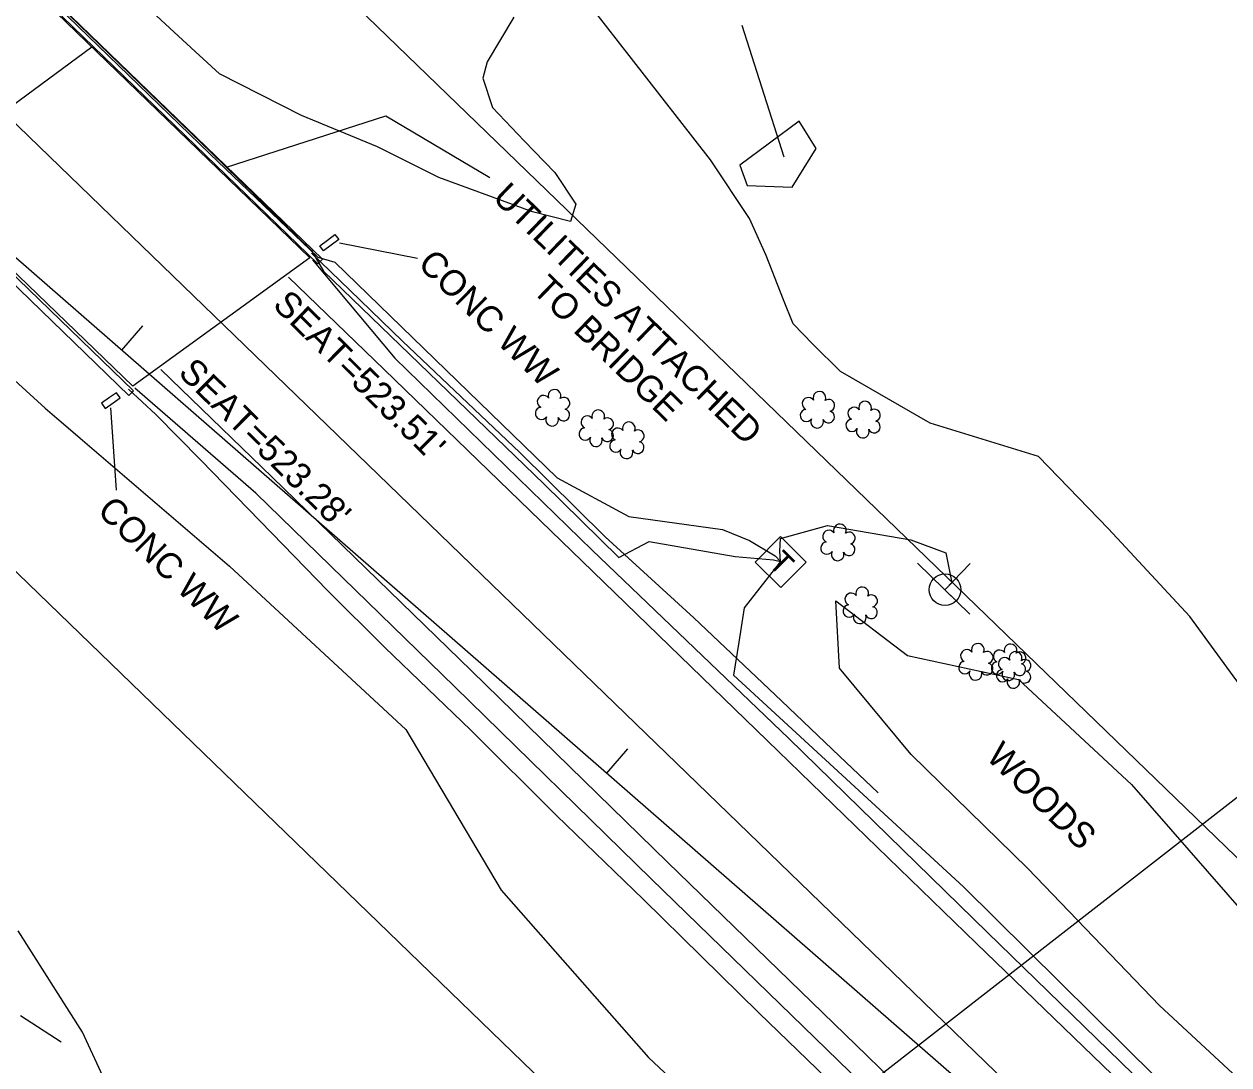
# Model space of a CAD drawing. Extents: x 1977096 to 1980486, y 845025 to 848427.
# Drawn here: x 1979075.8 to 1979263.1, y 846243.1 to 846404.9 of the extents above; entities that cross this region are included whole.
import ezdxf

# ---------------------------------------------------------------- set-up
doc = ezdxf.new("R2010")
doc.units = 0
for name, color, linetype in [('Exist Guardrail', 7, 'Continuous'), ('Exist Horizontal Alignment', 7, 'Continuous'), ('Exist Horizontal Baseline Alignment', 7, 'Continuous'), ('Exist Horizontal Baseline Alignment Tick small', 7, 'Continuous'), ('Exist Hydro Disappearing Stream CELL', 7, 'Continuous'), ('Exist Other Culture Area Outline', 7, 'Continuous'), ('Exist Other Culture Area Outline Text', 7, 'Continuous'), ('Exist Property Same Owner Line CELL', 7, 'Continuous'), ('Exist Right of Way Line', 7, 'Continuous'), ('Exist Roads Curbs', 7, 'Continuous'), ('Exist Roads EOP', 7, 'Continuous'), ('Exist Roads EOT', 7, 'Continuous'), ('Exist Structure Major Bridge Seam', 7, 'Continuous'), ('Exist Structure Major Bridge Seat Top Elevation', 7, 'Continuous'), ('Exist Structure Major Bridge WW', 7, 'Continuous'), ('Exist Structure Major Bridge WW Text', 7, 'Continuous'), ('Exist Structure Major Deck Tunnel Box Culvert', 7, 'Continuous'), ('Exist Utilities Power Joint Use Telephone CELL', 7, 'Continuous'), ('Exist Utilities Telephone Pedestal CELL', 7, 'Continuous'), ('Exist Utilities Telephone UG Cable SUE LOS B', 7, 'Continuous'), ('Exist Utilities Telephone UG Cable SUE LOS C', 7, 'Continuous'), ('Exist Vegetation Shrub CELL', 7, 'Continuous'), ('Exist Vegetation Woods Line', 7, 'Continuous'), ('Exist Vegetation Woods Line Text', 7, 'Continuous')]:
    doc.layers.add(name, color=color, linetype=linetype)

msp = doc.modelspace()

# ---------------------------------------------------------------- linework, layer by layer
at = {"layer": 'Exist Guardrail'}
for points in [[(1979120.53, 846369.31), (1979126.46, 846363.56), (1979134.68, 846355.61), (1979152.9, 846338.29), (1979166.16, 846325.21), (1979179.93, 846312.61), (1979193.55, 846299.73), (1979202.61, 846291.11), (1979208.59, 846285.42)], [(1979259.69, 846182.69), (1979249.62, 846192.61), (1979236.12, 846206.04), (1979223.28, 846219.01), (1979208.19, 846233.69), (1979190.05, 846251.2), (1979172.15, 846268.81), (1979158.61, 846281.9), (1979145.28, 846295.15), (1979131.93, 846308.01), (1979123.06, 846316.81), (1979114.36, 846325.76), (1979103.32, 846337.1), (1979096.34, 846344.2), (1979092.05, 846348.15)]]:
    msp.add_lwpolyline(points, dxfattribs=at)
at = {"layer": 'Exist Horizontal Alignment'}
msp.add_line((1978489.47, 846954.95), (1979491.73, 845985.98), dxfattribs=at)
at = {"layer": 'Exist Horizontal Baseline Alignment'}
msp.add_line((1978896.27, 846524.09), (1979767.77, 845764.02), dxfattribs=at)
at = {"layer": 'Exist Horizontal Baseline Alignment Tick small'}
for p, q in [((1979091.04, 846354.22), (1979094.32, 846357.99)), ((1979166.4, 846288.49), (1979169.69, 846292.26))]:
    msp.add_line(p, q, dxfattribs=at)
at = {"layer": 'Exist Hydro Disappearing Stream CELL'}
msp.add_line((1979075.29, 846250.81), (1979081.63, 846246.73), dxfattribs=at)
at = {"layer": 'Exist Other Culture Area Outline'}
msp.add_lwpolyline([(1979196.3, 846389.82), (1979187.11, 846382.94), (1979188.24, 846379.79), (1979195.25, 846379.53), (1979198.97, 846385.57), (1979196.3, 846389.82)], dxfattribs=at)
at = {"layer": 'Exist Other Culture Area Outline Text'}
msp.add_line((1979194, 846384.23), (1979187.46, 846404.69), dxfattribs=at)
msp.add_lwpolyline([(1979107.32, 846382.64), (1979132.06, 846390.64), (1979148.22, 846381.07)], dxfattribs=at)
at = {"layer": 'Exist Property Same Owner Line CELL'}
msp.add_lwpolyline([(1979292.37, 846303.36), (1979303.7, 846315.26), (1979077.67, 846139.38), (1979089, 846151.29)], dxfattribs=at)
at = {"layer": 'Exist Right of Way Line'}
for p, q in [((1978524.22, 846990.9), (1979641.56, 845910.68)), ((1978965.22, 846425.46), (1979456.98, 845950.04))]:
    msp.add_line(p, q, dxfattribs=at)
at = {"layer": 'Exist Roads Curbs'}
for p, q in [((1978950.41, 846534.47), (1979122.22, 846368.35)), ((1978949.71, 846533.75), (1979121.53, 846367.63)), ((1978921, 846514.01), (1979092.85, 846347.88)), ((1978920.3, 846513.29), (1979092.15, 846347.16)), ((1979121.53, 846367.63), (1979122.22, 846368.35)), ((1979092.15, 846347.16), (1979092.85, 846347.88))]:
    msp.add_line(p, q, dxfattribs=at)
at = {"layer": 'Exist Roads EOP'}
for points in [[(1979120.65, 846368.26), (1979133.49, 846352.99), (1979164.17, 846323.1), (1979194.73, 846293.87), (1979225.61, 846263.72), (1979255.68, 846234.45), (1979285.73, 846205.36), (1979315.37, 846176.53), (1979345.8, 846147.12), (1979377.72, 846116.63), (1979407.25, 846087.83), (1979438.13, 846057.9), (1979467.93, 846029.23), (1979498.8, 845999.18)], [(1979477.6, 845978.01), (1979446.84, 846007.88), (1979416.62, 846037.35), (1979386.7, 846066.33), (1979356.86, 846095.38), (1979326.24, 846125.39), (1979294.45, 846155.84), (1979265.05, 846184.42), (1979235.05, 846212.58), (1979204.24, 846241.97), (1979173.33, 846272.04), (1979142.8, 846301.86), (1979111.85, 846332.01), (1979093.06, 846348.31)]]:
    msp.add_lwpolyline(points, dxfattribs=at)
at = {"layer": 'Exist Roads EOT'}
for p, q in [((1979116.93, 846365.56), (1979131.83, 846351.23)), ((1979097.1, 846351.23), (1979114.39, 846334.48))]:
    msp.add_line(p, q, dxfattribs=at)
for points in [[(1979131.83, 846351.23), (1979162.6, 846321.41), (1979193.04, 846291.89), (1979223.84, 846262.02), (1979254.08, 846232.84), (1979284.13, 846203.74), (1979313.6, 846175.13), (1979344.26, 846145.52), (1979376, 846114.94), (1979405.65, 846086.18), (1979436.21, 846056.39), (1979465.96, 846027.1), (1979496.86, 845997.11)], [(1979114.39, 846334.48), (1979145.37, 846304.35), (1979175.87, 846274.62), (1979206.9, 846244.54), (1979237.19, 846215.01), (1979267.05, 846186.27), (1979296.58, 846157.89), (1979328.22, 846127.36), (1979359.02, 846097.46), (1979388.76, 846068.61), (1979418.86, 846039.37), (1979449, 846010.07), (1979479.81, 845980.17)]]:
    msp.add_lwpolyline(points, dxfattribs=at)
at = {"layer": 'Exist Structure Major Bridge Seam'}
msp.add_line((1979086.38, 846401.33), (1979058.73, 846380.94), dxfattribs=at)
at = {"layer": 'Exist Structure Major Bridge WW'}
for points in [[(1979121.81, 846370.45), (1979122.99, 846371.33), (1979124.17, 846372.21), (1979124.77, 846371.41), (1979123.59, 846370.53), (1979122.41, 846369.65), (1979121.81, 846370.45)], [(1979090.21, 846347.6), (1979089.14, 846346.86), (1979087.87, 846345.98), (1979088.44, 846345.16), (1979089.71, 846346.04), (1979090.78, 846346.78), (1979090.21, 846347.6)]]:
    msp.add_lwpolyline(points, dxfattribs=at)
at = {"layer": 'Exist Structure Major Bridge WW Text'}
for p, q in [((1979124.89, 846370.88), (1979137, 846368.51)), ((1979089.28, 846345.23), (1979090.17, 846332.47))]:
    msp.add_line(p, q, dxfattribs=at)
at = {"layer": 'Exist Structure Major Deck Tunnel Box Culvert'}
msp.add_lwpolyline([(1978949.98, 846533.2), (1979120.24, 846368.57), (1979092.73, 846348.59), (1978922.38, 846513.01), (1978949.98, 846533.2)], dxfattribs=at)
at = {"layer": 'Exist Utilities Power Joint Use Telephone CELL'}
msp.add_line((1979218.98, 846316.97), (1979218.98, 846316.97), dxfattribs=at)
msp.add_lwpolyline([(1979214.7, 846321.09), (1979222.85, 846313.2), (1979218.97, 846316.96), (1979222.88, 846321.03)], dxfattribs=at)
msp.add_circle((1979218.99, 846316.98), 2.45, dxfattribs=at)
at = {"layer": 'Exist Utilities Telephone Pedestal CELL'}
msp.add_line((1979193.41, 846321.34), (1979193.41, 846321.34), dxfattribs=at)
msp.add_lwpolyline([(1979189.49, 846321.27), (1979193.45, 846317.31), (1979197.4, 846321.27), (1979193.44, 846325.23), (1979189.49, 846321.27)], dxfattribs=at)
at = {"layer": 'Exist Utilities Telephone UG Cable SUE LOS B'}
for points in [[(1978827.65, 846546.54), (1978851.92, 846542.32), (1978879.52, 846535.99), (1978884.35, 846535.6), (1978891.83, 846534.67), (1978899.37, 846538.39), (1978920.22, 846556.85), (1978924.91, 846559.45), (1978950.09, 846536.12), (1978950.33, 846534.15), (1978987.97, 846497.66), (1979030.84, 846456.21), (1979068.41, 846419.87), (1979104.74, 846384.73), (1979121.49, 846368.64), (1979124.13, 846367.89), (1979158.73, 846334.37), (1979169.87, 846328.36), (1979184.39, 846326.33), (1979188.6, 846324.61), (1979192.59, 846322.26), (1979193.41, 846321.34)], [(1979193.41, 846321.34), (1979193.32, 846322.96), (1979193.4, 846324.92), (1979200.74, 846326.97), (1979213.68, 846324.75), (1979219.13, 846322.69), (1979220.06, 846318.06), (1979218.98, 846316.97)]]:
    msp.add_lwpolyline(points, dxfattribs=at)
at = {"layer": 'Exist Utilities Telephone UG Cable SUE LOS C'}
for points in [[(1978816.58, 846668.11), (1978851.59, 846633.51), (1978891.39, 846594.5), (1978926.18, 846560.72), (1978950.49, 846536.73), (1978950.45, 846534.27), (1978988.14, 846497.85), (1979031.03, 846456.38), (1979068.6, 846420.04), (1979104.92, 846384.91), (1979120.52, 846369.7), (1979122.4, 846366.47), (1979156.61, 846333.43), (1979168.3, 846321.97), (1979173, 846324.46), (1979186.35, 846322.12), (1979192.31, 846321.61), (1979193.41, 846321.34)], [(1979193.41, 846321.34), (1979192.65, 846320.39), (1979187.79, 846314.17), (1979186.96, 846308.83), (1979186.13, 846303.7), (1979221.88, 846270.8), (1979256.83, 846236.2), (1979291.06, 846202.44), (1979328.81, 846166.03), (1979367.53, 846128.09), (1979406.07, 846091.3), (1979445.38, 846052.99), (1979477.33, 846021.94)]]:
    msp.add_lwpolyline(points, dxfattribs=at)
at = {"layer": 'Exist Vegetation Shrub CELL'}
for p, q in [((1979158.06, 846345.08), (1979158.06, 846345.08)), ((1979199.24, 846344.76), (1979199.24, 846344.76)), ((1979164.86, 846341.89), (1979164.86, 846341.89)), ((1979206.34, 846343.23), (1979206.34, 846343.23)), ((1979169.62, 846340.02), (1979169.62, 846340.02)), ((1979202.43, 846324.15), (1979202.43, 846324.15)), ((1979205.89, 846314.37), (1979205.89, 846314.37)), ((1979223.87, 846305.59), (1979223.87, 846305.59)), ((1979228.95, 846305.51), (1979228.95, 846305.51)), ((1979229.74, 846304.33), (1979229.74, 846304.33))]:
    msp.add_line(p, q, dxfattribs=at)
for centre, radius, start, end in [((1979156.58, 846346.21), 0.968, 35.8908, 245.4216), ((1979158.29, 846347.12), 0.99, 334.8391, 200.4717), ((1979199.47, 846346.8), 0.99, 334.8391, 200.4717), ((1979156.26, 846344.38), 0.955, 95.1099, 327.9534), ((1979159.73, 846345.95), 0.929, 284.4567, 126.0861), ((1979197.76, 846345.89), 0.968, 35.8908, 245.4216), ((1979200.91, 846345.63), 0.929, 284.4567, 126.0861), ((1979204.86, 846344.36), 0.968, 35.8908, 245.4216), ((1979206.57, 846345.27), 0.99, 334.8391, 200.4717), ((1979157.93, 846343.4), 0.984, 151.2797, 21.387), ((1979159.7, 846344.15), 0.937, 204.9913, 73.4601), ((1979163.38, 846343.02), 0.968, 35.8908, 245.4216), ((1979165.09, 846343.93), 0.99, 334.8391, 200.4717), ((1979166.53, 846342.76), 0.929, 284.4567, 126.0861), ((1979197.44, 846344.06), 0.955, 95.1099, 327.9534), ((1979199.11, 846343.08), 0.984, 151.2797, 21.387), ((1979200.87, 846343.83), 0.937, 204.9913, 73.4601), ((1979204.54, 846342.53), 0.955, 95.1099, 327.9534), ((1979208.01, 846344.1), 0.929, 284.4567, 126.0861), ((1979163.06, 846341.19), 0.955, 95.1099, 327.9534), ((1979166.5, 846340.96), 0.937, 204.9913, 73.4601), ((1979168.14, 846341.14), 0.968, 35.8908, 245.4216), ((1979169.85, 846342.06), 0.99, 334.8391, 200.4717), ((1979171.29, 846340.88), 0.929, 284.4567, 126.0861), ((1979206.21, 846341.55), 0.984, 151.2797, 21.387), ((1979207.98, 846342.3), 0.937, 204.9913, 73.4601), ((1979164.73, 846340.21), 0.984, 151.2797, 21.387), ((1979167.82, 846339.31), 0.955, 95.1099, 327.9534), ((1979171.26, 846339.09), 0.937, 204.9913, 73.4601), ((1979169.49, 846338.33), 0.984, 151.2797, 21.387), ((1979202.65, 846326.19), 0.99, 334.8391, 200.4717), ((1979200.94, 846325.27), 0.968, 35.8908, 245.4216), ((1979204.1, 846325.01), 0.929, 284.4567, 126.0861), ((1979200.63, 846323.44), 0.955, 95.1099, 327.9534), ((1979202.3, 846322.46), 0.984, 151.2797, 21.387), ((1979204.06, 846323.22), 0.937, 204.9913, 73.4601), ((1979206.12, 846316.41), 0.99, 334.8391, 200.4717), ((1979204.41, 846315.5), 0.968, 35.8908, 245.4216), ((1979207.56, 846315.24), 0.929, 284.4567, 126.0861), ((1979204.09, 846313.67), 0.955, 95.1099, 327.9534), ((1979207.53, 846313.44), 0.937, 204.9913, 73.4601), ((1979205.76, 846312.69), 0.984, 151.2797, 21.387), ((1979224.09, 846307.63), 0.99, 334.8391, 200.4717), ((1979229.18, 846307.55), 0.99, 334.8391, 200.4717), ((1979222.38, 846306.71), 0.968, 35.8908, 245.4216), ((1979225.54, 846306.46), 0.929, 284.4567, 126.0861), ((1979227.47, 846306.64), 0.968, 35.8908, 245.4216), ((1979228.25, 846305.46), 0.968, 35.8908, 245.4216), ((1979229.97, 846306.37), 0.99, 334.8391, 200.4717), ((1979230.63, 846306.38), 0.929, 284.4567, 126.0861), ((1979231.41, 846305.2), 0.929, 284.4567, 126.0861), ((1979222.07, 846304.88), 0.955, 95.1099, 327.9534), ((1979223.74, 846303.9), 0.984, 151.2797, 21.387), ((1979225.5, 846304.66), 0.937, 204.9913, 73.4601), ((1979227.15, 846304.81), 0.955, 95.1099, 327.9534), ((1979227.94, 846303.63), 0.955, 95.1099, 327.9534), ((1979228.83, 846303.83), 0.984, 151.2797, 21.387), ((1979230.59, 846304.58), 0.937, 204.9913, 73.4601), ((1979231.37, 846303.4), 0.937, 204.9913, 73.4601), ((1979229.61, 846302.65), 0.984, 151.2797, 21.387)]:
    msp.add_arc(centre, radius, start, end, dxfattribs=at)
at = {"layer": 'Exist Vegetation Woods Line'}
for points in [[(1979106.21, 846397.14), (1979100.52, 846402.41), (1979086.85, 846415.09)], [(1979216.68, 846342.89), (1979202.74, 846350.9), (1979198.43, 846355.14), (1979195.39, 846358.28), (1979193.86, 846362.02), (1979191.18, 846368.92), (1979188.62, 846374.68), (1979182.56, 846383.8), (1979170.24, 846399.53), (1979162.18, 846409.95)], [(1979151.98, 846405.97), (1979147.81, 846399.03), (1979147.14, 846396.49), (1979148.66, 846391.91), (1979153.57, 846386.76), (1979158.35, 846381.83), (1979161.61, 846376.88), (1979160.8, 846374.22), (1979154.87, 846375.72), (1979140.32, 846381.03), (1979130.76, 846385.83), (1979118.94, 846390.68), (1979106.21, 846397.14)], [(1979062.47, 846360.32), (1979079.12, 846345.19), (1979107.76, 846320.62), (1979135.17, 846295.24), (1979150.01, 846270.28), (1979172.92, 846244.25), (1979193.4, 846225.03)], [(1979312.41, 846251.59), (1979298.73, 846264.44), (1979279.74, 846280.75), (1979268.15, 846297.65), (1979257.02, 846312.79), (1979244.42, 846326.45), (1979233.52, 846337.68), (1979216.68, 846342.89)], [(1979285.06, 846221.98), (1979252.33, 846252.35), (1979231.85, 846273.63), (1979213.75, 846291.36), (1979202.59, 846304.76), (1979202.01, 846315.27), (1979213.14, 846306.77), (1979230.39, 846303.01), (1979247.97, 846286.7), (1979265.81, 846266.31), (1979276.02, 846252.06), (1979290.77, 846231.67)], [(1979091.22, 846234.53), (1979084.91, 846248.23), (1979074.9, 846263.95)]]:
    msp.add_lwpolyline(points, dxfattribs=at)

# ---------------------------------------------------------------- texts
at = {"layer": 'Exist Other Culture Area Outline Text'}
for s, p in [('UTILITIES ATTACHED', (1979148.49, 846377.73)), ('TO BRIDGE', (1979154.65, 846363.39))]:
    msp.add_text(s, height=4, rotation=315.8604, dxfattribs=at).set_placement(p)
at = {"layer": 'Exist Structure Major Bridge Seat Top Elevation'}
for s, p in [("SEAT=523.51'", (1979114.32, 846361.05)), ("SEAT=523.28'", (1979099.64, 846350.51))]:
    msp.add_text(s, height=4, rotation=315.4793, dxfattribs=at).set_placement(p)
at = {"layer": 'Exist Structure Major Bridge WW Text'}
for p in [(1979136.86, 846367.4), (1979087.04, 846329.03)]:
    msp.add_text('CONC WW', height=4, rotation=315.6407, dxfattribs=at).set_placement(p)
at = {"layer": 'Exist Utilities Telephone Pedestal CELL'}
msp.add_text('T', height=3.42, rotation=315.0641, dxfattribs=at).set_placement((1979191.4, 846320.93))
at = {"layer": 'Exist Vegetation Woods Line Text'}
msp.add_text('WOODS', height=4, rotation=315.6543, dxfattribs=at).set_placement((1979225.19, 846290.82))

doc.saveas('drawing.dxf')
